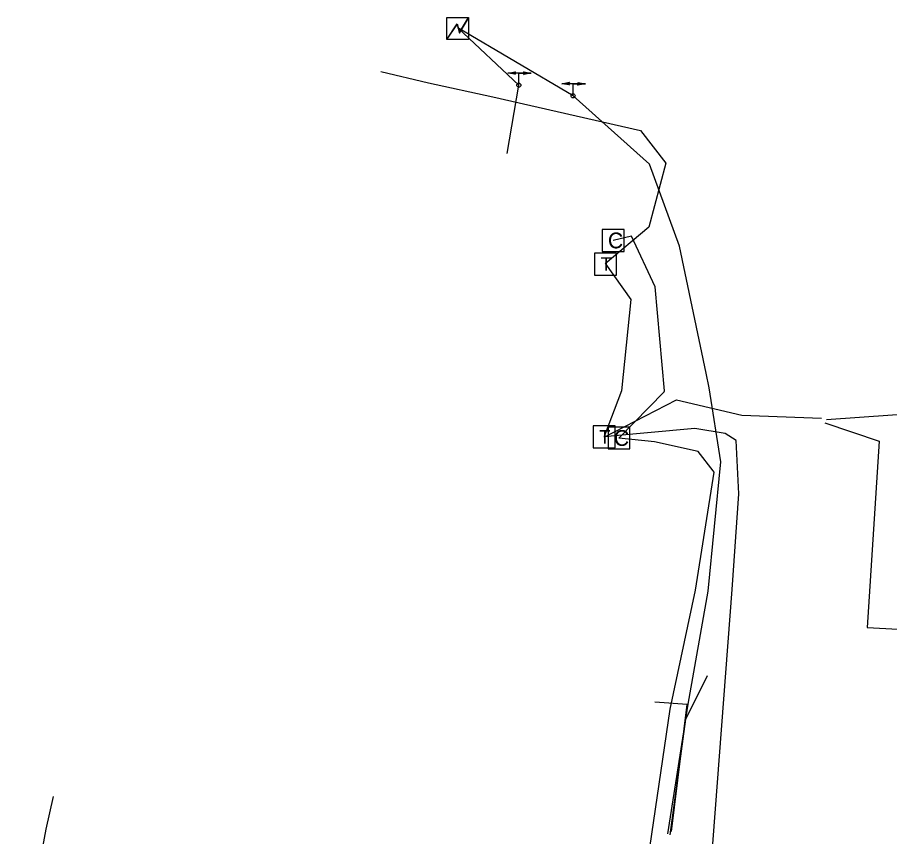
# Model space of a CAD drawing. Extents: x 2070721 to 2083340, y 729290 to 737883.
# Drawn here: x 2082142.2 to 2082363.4, y 736489 to 736696.6 of the extents above; entities that cross this region are included whole.
import ezdxf

# ---------------------------------------------------------------- set-up
doc = ezdxf.new("R2010")
doc.units = 0
for name, color, linetype in [('Exist Utilities Power Change of Service SUE CELL', 7, 'Continuous'), ('Exist Utilities Power Transformer CELL', 7, 'Continuous'), ('Exist Utilities Power UG Cable SUE LOS B', 7, 'Continuous'), ('Exist Utilities Power UG Cable SUE LOS C', 7, 'Continuous'), ('Exist Utilities Telephone Pedestal CELL', 7, 'Continuous'), ('Exist Utilities Telephone UG Cable SUE LOS C', 7, 'Continuous'), ('Exist Utilities TV Pedestal CELL', 7, 'Continuous'), ('Exist Utilities TV UG Cable SUE LOS C', 7, 'Continuous'), ('Exist Utilities TV UG FO Cable SUE LOS C', 7, 'Continuous')]:
    doc.layers.add(name, color=color, linetype=linetype)

msp = doc.modelspace()

# ---------------------------------------------------------------- linework, layer by layer
at = {"layer": 'Exist Utilities Power Change of Service SUE CELL'}
for p, q in [((2082272.52, 736682.55), (2082266.55, 736682.55)), ((2082269.38, 736679.47), (2082269.38, 736682.55)), ((2082269.38, 736682.55), (2082272.52, 736682.55)), ((2082269.38, 736679.47), (2082269.38, 736679.47)), ((2082286.25, 736679.84), (2082280.29, 736679.84)), ((2082283.12, 736676.76), (2082283.12, 736679.84)), ((2082283.12, 736679.84), (2082286.25, 736679.84)), ((2082283.12, 736676.76), (2082283.12, 736676.76))]:
    msp.add_line(p, q, dxfattribs=at)
for points in [[(2082266.55, 736682.55), (2082268.52, 736682.89), (2082268.11, 736682.55), (2082268.49, 736682.25)], [(2082272.52, 736682.55), (2082270.55, 736682.21), (2082270.97, 736682.55), (2082270.58, 736682.86)], [(2082280.29, 736679.84), (2082282.26, 736680.19), (2082281.84, 736679.84), (2082282.22, 736679.54)], [(2082286.25, 736679.84), (2082284.28, 736679.5), (2082284.7, 736679.84), (2082284.32, 736680.15)]]:
    msp.add_lwpolyline(points, close=True, dxfattribs=at)
for centre in [(2082269.38, 736679.47), (2082283.12, 736676.76)]:
    msp.add_circle(centre, 0.517, dxfattribs=at)
at = {"layer": 'Exist Utilities Power Transformer CELL'}
msp.add_line((2082253.92, 736694.03), (2082253.92, 736694.03), dxfattribs=at)
msp.add_lwpolyline([(2082251.08, 736696.64), (2082256.63, 736696.64), (2082256.63, 736691.09), (2082251.08, 736691.09)], close=True, dxfattribs=at)
for points in [[(2082251.08, 736691.09), (2082253.72, 736695.03), (2082254.35, 736692.82), (2082256.63, 736696.64)], [(2082251.15, 736691.09), (2082253.72, 736694.82), (2082254.31, 736692.64), (2082256.63, 736696.49)]]:
    msp.add_lwpolyline(points, dxfattribs=at)
at = {"layer": 'Exist Utilities Power UG Cable SUE LOS B'}
msp.add_line((2082266.41, 736662.13), (2082269.38, 736679.47), dxfattribs=at)
for points in [[(2082316.9, 736606.43), (2082310.09, 736638.69), (2082302.53, 736659.4), (2082283.12, 736676.76)], [(2082307.19, 736489.63), (2082312.29, 736522.5), (2082317.39, 736551.2), (2082320.59, 736583.96), (2082317.63, 736602.74), (2082316.9, 736606.43)], [(2082307.78, 736489.42), (2082311.73, 736518.74), (2082317.25, 736529.76)], [(2082308.12, 736490.25), (2082312.09, 736522.45), (2082303.83, 736523.07)], [(2082142.24, 736451.57), (2082149.5, 736490.83), (2082151.41, 736499.09)]]:
    msp.add_lwpolyline(points, dxfattribs=at)
at = {"layer": 'Exist Utilities Power UG Cable SUE LOS C'}
for p in [(2082269.38, 736679.47), (2082283.12, 736676.76)]:
    msp.add_line(p, (2082253.92, 736694.03), dxfattribs=at)
at = {"layer": 'Exist Utilities Telephone Pedestal CELL'}
for p, q in [((2082291.25, 736634.14), (2082291.25, 736634.14)), ((2082290.9, 736590.33), (2082290.9, 736590.33))]:
    msp.add_line(p, q, dxfattribs=at)
for points in [[(2082288.52, 736631.32), (2082294.11, 736631.32), (2082294.11, 736636.91), (2082288.52, 736636.91), (2082288.52, 736631.32)], [(2082288.18, 736587.5), (2082293.77, 736587.5), (2082293.77, 736593.09), (2082288.18, 736593.09), (2082288.18, 736587.5)]]:
    msp.add_lwpolyline(points, dxfattribs=at)
at = {"layer": 'Exist Utilities Telephone UG Cable SUE LOS C'}
for points in [[(2082234.39, 736682.96), (2082246.45, 736680.07), (2082262.79, 736676.47), (2082300.22, 736668.01), (2082306.68, 736659.69), (2082302.32, 736643.44), (2082291.24, 736634.14)], [(2082291.31, 736634.18), (2082297.74, 736625.14), (2082295.42, 736602), (2082290.98, 736590.39)], [(2082291.01, 736590.2), (2082309.31, 736599.68), (2082325.94, 736595.82), (2082346.11, 736595.07)], [(2082313.36, 736418.13), (2082323.5, 736551.56), (2082325.19, 736575.84), (2082324.51, 736589.38), (2082321.65, 736591.13), (2082314.03, 736592.42), (2082290.9, 736590.33)]]:
    msp.add_lwpolyline(points, dxfattribs=at)
at = {"layer": 'Exist Utilities TV Pedestal CELL'}
for p, q in [((2082293.28, 736640.1), (2082293.28, 736640.1)), ((2082294.78, 736590.01), (2082294.78, 736590.01))]:
    msp.add_line(p, q, dxfattribs=at)
for points in [[(2082290.51, 736637.32), (2082296.06, 736637.32), (2082296.06, 736642.87), (2082290.51, 736642.87), (2082290.51, 736637.32)], [(2082292, 736587.24), (2082297.55, 736587.24), (2082297.55, 736592.79), (2082292, 736592.79), (2082292, 736587.24)]]:
    msp.add_lwpolyline(points, dxfattribs=at)
at = {"layer": 'Exist Utilities TV UG Cable SUE LOS C'}
for points in [[(2082294.76, 736589.99), (2082306.2, 736601.68), (2082306.27, 736601.95), (2082303.96, 736628.34), (2082297.91, 736641.15), (2082293.29, 736640.09)], [(2082346.94, 736593.86), (2082360.72, 736589.21), (2082357.72, 736541.97), (2082403.21, 736539.49), (2082428.03, 736538.87), (2082478.07, 736536.61), (2082484.59, 736536.15), (2082535.98, 736537.5), (2082560.91, 736538.33), (2082609.93, 736548.58), (2082615.28, 736549.68), (2082630.73, 736556.71), (2082655.26, 736576.14), (2082659.68, 736579.26), (2082669.26, 736584.45)], [(2082318.86, 736581.32), (2082318.64, 736581.7), (2082314.87, 736586.57), (2082303.81, 736589.07), (2082294.76, 736590)], [(2082291.62, 736436.42), (2082301.26, 736476.92), (2082307.72, 736521.26), (2082314.13, 736551.45), (2082318.86, 736581.32), (2082318.86, 736581.32)]]:
    msp.add_lwpolyline(points, dxfattribs=at)
at = {"layer": 'Exist Utilities TV UG FO Cable SUE LOS C'}
msp.add_lwpolyline([(2082347.36, 736594.7), (2082407.12, 736598.92), (2082432.73, 736605.4), (2082485.1, 736604.34), (2082529.04, 736601.5), (2082560.83, 736601.5), (2082602.16, 736608.48), (2082660.87, 736631.23), (2082699.66, 736656.83), (2082708.35, 736665.58)], dxfattribs=at)

# ---------------------------------------------------------------- texts
at = {"layer": 'Exist Utilities Telephone Pedestal CELL'}
for p in [(2082290.11, 736632.43), (2082289.77, 736588.61)]:
    msp.add_text('T', height=3.42, dxfattribs=at).set_placement(p)
at = {"layer": 'Exist Utilities TV Pedestal CELL'}
for p in [(2082291.97, 736638.1), (2082293.47, 736588.01)]:
    msp.add_text('C', height=4, dxfattribs=at).set_placement(p)

doc.saveas('drawing.dxf')
